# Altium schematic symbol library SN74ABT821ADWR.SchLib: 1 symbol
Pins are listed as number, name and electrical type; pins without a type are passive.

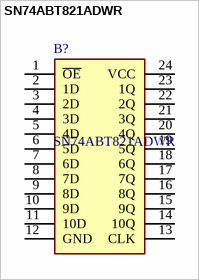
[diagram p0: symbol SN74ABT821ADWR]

## SN74ABT821ADWR
designator B?
10-Bit Bus Interface Flip-Flops With 3-State Outputs; Manufacturer_Name: Texas Instruments; Geometry.Height: 2.65mm
footprint SOIC127P1030X265-24N
pins: 1 ~{OE}, 2 1D, 3 2D, 4 3D, 5 4D, 6 5D, 7 6D, 8 7D, 9 8D, 10 9D, 11 10D, 12 GND, 13 CLK, 14 10Q, 15 9Q, 16 8Q, 17 7Q, 18 6Q, 19 5Q, 20 4Q, 21 3Q, 22 2Q, 23 1Q, 24 VCC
